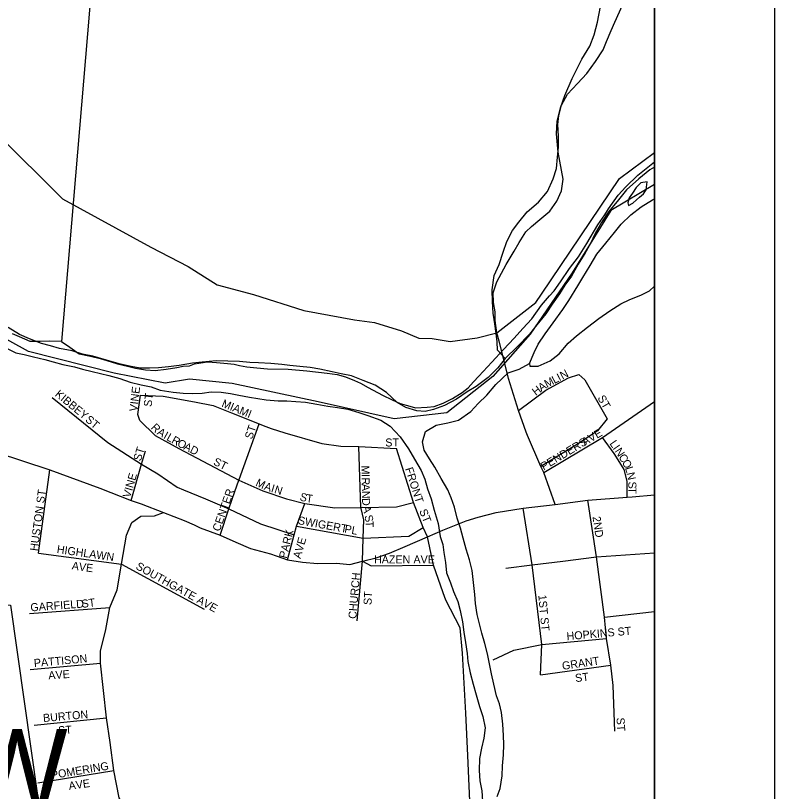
# Model space of a CAD drawing. Extents: x 0 to 34, y -4 to 22.
# Drawn here: x 8.368 to 9, y 16.667 to 17.313 of the extents above; entities that cross this region are included whole.
import ezdxf

# ---------------------------------------------------------------- set-up
doc = ezdxf.new("R2010")
doc.units = 0
for name, color, linetype in [('GM_X_City_Street', 7, 'Continuous'), ('GM_X_City_Street_Text', 7, 'Continuous'), ('GM_X_Corporation', 7, 'Continuous'), ('GM_X_Corporation_Text', 7, 'Continuous'), ('GM_X_County_Road', 7, 'Continuous'), ('GM_X_County_ROW', 7, 'Continuous'), ('GM_X_Major_River', 7, 'Continuous'), ('GM_X_Minor_River', 7, 'Continuous'), ('GM_X_Section', 7, 'Continuous'), ('GM_X_State_Route', 7, 'Continuous'), ('GM_X_Township', 7, 'Continuous'), ('GM_X_US_Route', 7, 'Continuous'), ('SH_Data', 7, 'Continuous'), ('SN_P_Text', 7, 'Continuous')]:
    doc.layers.add(name, color=color, linetype=linetype)

msp = doc.modelspace()

# ---------------------------------------------------------------- linework, layer by layer
at = {"layer": 'GM_X_City_Street'}
msp.add_line((8.85843, 16.81262), (8.9, 16.81728), dxfattribs=at)
for points in [[(8.78674, 16.98474), (8.80951, 17.00166), (8.82863, 17.01177), (8.83701, 17.01462), (8.84223, 17.01019), (8.86072, 16.97763), (8.85266, 16.96768), (8.83737, 16.9574), (8.80546, 16.93796)], [(8.39859, 16.99537), (8.44502, 16.95792), (8.47298, 16.93995), (8.48647, 16.93179), (8.50261, 16.9208), (8.50792, 16.91861)], [(8.47149, 16.97623), (8.46982, 16.98122), (8.47215, 16.99736)], [(8.47215, 16.99736), (8.49113, 16.99653), (8.51709, 16.9917), (8.53256, 16.98871), (8.54788, 16.98271), (8.57085, 16.9734), (8.57441, 16.97211)], [(8.80792, 16.9329), (8.85693, 16.96214), (8.9, 16.99201)], [(8.47149, 16.97623), (8.4843, 16.96391), (8.50394, 16.95309), (8.55395, 16.92649)], [(8.55425, 16.92731), (8.57085, 16.9734)], [(8.57441, 16.97211), (8.581, 16.96974), (8.59231, 16.96591), (8.62327, 16.95708), (8.63892, 16.95492), (8.65389, 16.95459), (8.68518, 16.95292)], [(8.8725, 16.93923), (8.86657, 16.94871), (8.85693, 16.96214)], [(8.46433, 16.90982), (8.47298, 16.93995), (8.47631, 16.95093)], [(8.6558, 16.90311), (8.6556, 16.90393), (8.65389, 16.95459)], [(8.71115, 16.87936), (8.70749, 16.88719), (8.69949, 16.90816), (8.68518, 16.95292)], [(8.87741, 16.91248), (8.87731, 16.92579), (8.87479, 16.93558), (8.8725, 16.93923)], [(8.38722, 16.86588), (8.39659, 16.93528)], [(8.53841, 16.88097), (8.54577, 16.90264), (8.55074, 16.91729), (8.55395, 16.92649), (8.55425, 16.92731)], [(8.55395, 16.92649), (8.57401, 16.91764), (8.59364, 16.91099), (8.60896, 16.90733), (8.63409, 16.90349), (8.6556, 16.90393), (8.68535, 16.90433), (8.69949, 16.90816)], [(8.50792, 16.91861), (8.52641, 16.91099), (8.54577, 16.90264), (8.57201, 16.89035), (8.60016, 16.88123)], [(8.59449, 16.86034), (8.60016, 16.88123), (8.60207, 16.88825), (8.60896, 16.90733)], [(8.8671, 16.7177), (8.86559, 16.75571), (8.86376, 16.77268), (8.8601, 16.79482), (8.85843, 16.81262), (8.85194, 16.86272), (8.84462, 16.90999)], [(8.45661, 16.6587), (8.45445, 16.66217), (8.45001, 16.68493), (8.44697, 16.70815), (8.44392, 16.72884), (8.43897, 16.77442), (8.43894, 16.78418), (8.44325, 16.8022), (8.44661, 16.82062), (8.45267, 16.8352), (8.45638, 16.8567), (8.46053, 16.88077), (8.465, 16.89151), (8.47232, 16.89667), (8.4838, 16.89684), (8.49129, 16.89967)], [(8.65689, 16.85922), (8.65756, 16.87837), (8.65805, 16.89351), (8.6558, 16.90311)], [(8.80518, 16.76469), (8.80618, 16.78982), (8.79836, 16.85606), (8.79087, 16.90333)], [(8.60207, 16.88825), (8.65756, 16.87837), (8.69567, 16.88003), (8.70749, 16.88719)], [(8.72427, 16.83271), (8.71605, 16.8559), (8.71115, 16.87936)], [(8.79835, 16.85606), (8.79836, 16.85606), (8.82365, 16.85922), (8.85194, 16.86272), (8.9, 16.86611)], [(8.38722, 16.86588), (8.45638, 16.8567)], [(8.45638, 16.8567), (8.52523, 16.81923)], [(8.65265, 16.8094), (8.65689, 16.85922)], [(8.65689, 16.85922), (8.66421, 16.85523), (8.71605, 16.8559)], [(8.77622, 16.8534), (8.79835, 16.85606)], [(8.37984, 16.81574), (8.44661, 16.82062)], [(8.76574, 16.77718), (8.78287, 16.78516), (8.80618, 16.78982), (8.8601, 16.79482)], [(8.38019, 16.76902), (8.43897, 16.77442)], [(8.80518, 16.76469), (8.86376, 16.77268)], [(8.3835, 16.72265), (8.44392, 16.72884)], [(8.3866, 16.67458), (8.45001, 16.68493)]]:
    msp.add_lwpolyline(points, dxfattribs=at)
at = {"layer": 'GM_X_Corporation'}
msp.add_lwpolyline([(8.9, 15.91505), (8.9, 17.17268), (8.86365, 17.15124), (8.83148, 17.09921), (8.79666, 17.04827), (8.7655, 17.0128), (8.72719, 16.98276), (8.68332, 16.97765), (8.6202, 16.99174), (8.54854, 17.007), (8.51306, 17.01061), (8.49272, 17.00737), (8.45036, 17.01561), (8.37901, 17.0338), (8.33444, 17.0581), (8.26206, 17.10064), (8.16412, 17.15042), (8.06988, 17.19641), (8.05808, 17.08586), (8.09498, 17.02502), (8.15329, 16.9257), (8.21598, 16.82312), (8.36391, 16.8226), (8.39233, 16.62295)], dxfattribs=at)
at = {"layer": 'GM_X_County_Road'}
for points in [[(8.16162, 17.33442), (8.21917, 17.29622), (8.33224, 17.2399), (8.34171, 17.23144), (8.35262, 17.21493), (8.40719, 17.16075), (8.48075, 17.12065), (8.51172, 17.10458), (8.53602, 17.08917), (8.56635, 17.08122), (8.60808, 17.06776), (8.65047, 17.06002), (8.66696, 17.058), (8.6895, 17.05093), (8.70397, 17.04488), (8.71507, 17.04454), (8.72988, 17.04219), (8.75242, 17.04522), (8.76891, 17.04925), (8.80121, 17.07449), (8.80599, 17.08155)], [(8.80599, 17.08155), (8.87105, 17.17764), (8.9, 17.1995)]]:
    msp.add_lwpolyline(points, dxfattribs=at)
at = {"layer": 'GM_X_County_ROW'}
msp.add_lwpolyline([(8.72549, 16.60607), (8.73149, 16.61464), (8.74254, 16.63166), (8.74682, 16.64674), (8.74471, 16.69729), (8.74316, 16.73269), (8.74034, 16.78248), (8.73836, 16.80364), (8.72637, 16.82677), (8.72427, 16.83271)], dxfattribs=at)
at = {"layer": 'GM_X_Major_River'}
for points in [[(8.9, 17.18709), (8.89614, 17.18495), (8.88711, 17.17742), (8.87671, 17.16833), (8.86896, 17.15863), (8.86178, 17.14999), (8.85593, 17.14105), (8.85061, 17.13183), (8.84691, 17.12363), (8.84215, 17.1152), (8.83657, 17.10652), (8.83096, 17.0965), (8.82541, 17.08889), (8.82094, 17.08178), (8.81483, 17.07312), (8.80954, 17.06496), (8.80207, 17.0558), (8.79599, 17.0482), (8.78581, 17.03749), (8.77566, 17.02786), (8.76957, 17.02026), (8.7616, 17.01217), (8.75151, 17.00467), (8.74416, 17.00004), (8.73517, 16.99412), (8.72513, 16.98876), (8.71622, 16.98551), (8.70921, 16.98381), (8.70227, 16.98425), (8.69297, 16.98716), (8.68585, 16.99135), (8.67697, 16.99959), (8.66749, 17.0057), (8.65742, 17.0097), (8.64788, 17.01341), (8.6391, 17.01524), (8.63164, 17.01676), (8.62153, 17.01915), (8.61353, 17.02042), (8.60472, 17.02117), (8.59645, 17.02218), (8.58978, 17.02288), (8.5807, 17.02365), (8.57027, 17.02417), (8.56332, 17.02462), (8.55451, 17.02537), (8.54488, 17.02561), (8.53525, 17.02585), (8.52345, 17.02481), (8.5154, 17.02394), (8.50437, 17.02208), (8.49551, 17.02097), (8.48719, 17.0201), (8.47969, 17.01976), (8.47193, 17.01995), (8.46447, 17.02121), (8.45436, 17.0236), (8.44373, 17.02654), (8.43257, 17.02976), (8.42379, 17.03158), (8.41529, 17.0342), (8.40464, 17.03634), (8.3972, 17.03839), (8.38976, 17.04045), (8.37968, 17.04418), (8.37148, 17.04786), (8.362, 17.05371)], [(8.89401, 17.17484), (8.88864, 17.17418), (8.88479, 17.17026), (8.88172, 17.16553), (8.87894, 17.16159), (8.87777, 17.15761), (8.87851, 17.15519), (8.88204, 17.15724), (8.88506, 17.1601), (8.88752, 17.16218)], [(8.88752, 17.16218), (8.89108, 17.16503), (8.8933, 17.16818), (8.89401, 17.17484)], [(8.76919, 16.66317), (8.77151, 16.67006), (8.77338, 16.68044), (8.7736, 16.68872), (8.77437, 16.69805), (8.77459, 16.7066), (8.77452, 16.71409), (8.77396, 16.72346), (8.7726, 16.73311), (8.77118, 16.74037), (8.76868, 16.74711), (8.76625, 16.75679), (8.76433, 16.7654), (8.76244, 16.77506), (8.76102, 16.78205), (8.75883, 16.79066), (8.75638, 16.79927), (8.75419, 16.80815), (8.7525, 16.81487), (8.75113, 16.82399), (8.75051, 16.83149), (8.74943, 16.84141), (8.74835, 16.85133), (8.74617, 16.8602), (8.74319, 16.8691), (8.74075, 16.87825), (8.73855, 16.88659), (8.73583, 16.89494), (8.73365, 16.90408), (8.73091, 16.9119), (8.72814, 16.91866), (8.72249, 16.92788), (8.71711, 16.93737), (8.71275, 16.94443), (8.70838, 16.95149), (8.70695, 16.95848), (8.70932, 16.96724), (8.71829, 16.97236), (8.72797, 16.97426), (8.73687, 16.9767), (8.74722, 16.98366), (8.75328, 16.99046), (8.76042, 16.9975), (8.76814, 17.00613), (8.7783, 17.01603), (8.78747, 17.01901), (8.7959, 17.02388), (8.79987, 17.03286), (8.80326, 17.03973), (8.80911, 17.0484), (8.81577, 17.05759), (8.82382, 17.06862), (8.82883, 17.07624), (8.83637, 17.08835), (8.84057, 17.09546), (8.84644, 17.1052), (8.85204, 17.11468), (8.8595, 17.12385), (8.86669, 17.13276), (8.87249, 17.13983), (8.88045, 17.14739), (8.88892, 17.15412), (8.89844, 17.16003), (8.9, 17.16095)], [(8.35837, 17.0375), (8.36841, 17.0327), (8.37533, 17.03119), (8.38305, 17.02939), (8.39262, 17.02702), (8.39953, 17.02524), (8.4075, 17.0229), (8.41709, 17.02106), (8.424, 17.01901), (8.43198, 17.01721), (8.43889, 17.01543), (8.44581, 17.01366), (8.45485, 17.01129), (8.4636, 17.00813), (8.47265, 17.00604), (8.48116, 17.00422), (8.48859, 17.00163), (8.49925, 17.00002), (8.50779, 16.99901), (8.51555, 16.99882), (8.52359, 16.99915), (8.53111, 17.00003), (8.5394, 16.99982), (8.54713, 16.99883), (8.55405, 16.99732), (8.56285, 16.99576), (8.57671, 16.99354), (8.58686, 16.99275), (8.59408, 16.99257), (8.60156, 16.99212), (8.60958, 16.99165), (8.6189, 16.98981), (8.62823, 16.98824), (8.63623, 16.98724), (8.64476, 16.98569), (8.65406, 16.98305), (8.66148, 16.98046), (8.67235, 16.97645), (8.67999, 16.97145), (8.68833, 16.96268), (8.69529, 16.95262), (8.70016, 16.94421), (8.7058, 16.93472), (8.70883, 16.92742), (8.71103, 16.91935), (8.71429, 16.91098), (8.71673, 16.90157), (8.71992, 16.89053), (8.72178, 16.87979), (8.72375, 16.87306), (8.72465, 16.86635), (8.72604, 16.85803), (8.72689, 16.84946), (8.73015, 16.84109), (8.73265, 16.83408), (8.73645, 16.8257), (8.73839, 16.81816), (8.74029, 16.80876), (8.74141, 16.80018), (8.74279, 16.79159), (8.74417, 16.78247), (8.74479, 16.77577), (8.74669, 16.76637), (8.74912, 16.75669), (8.75157, 16.74781), (8.75453, 16.73811), (8.75726, 16.72976), (8.75916, 16.72035), (8.75813, 16.71182), (8.75605, 16.70359), (8.75448, 16.69481), (8.75423, 16.68493), (8.75481, 16.67636), (8.75647, 16.66803), (8.75678, 16.65947)]]:
    msp.add_lwpolyline(points, dxfattribs=at)
at = {"layer": 'GM_X_Minor_River'}
for points in [[(8.77566, 17.02786), (8.76942, 17.03496), (8.76905, 17.04165), (8.76816, 17.04863), (8.7673, 17.05666), (8.76565, 17.06553), (8.76511, 17.07543), (8.76482, 17.08506), (8.76674, 17.09704), (8.77071, 17.10603), (8.77419, 17.11636), (8.7771, 17.12538), (8.78188, 17.13435), (8.78715, 17.14143), (8.79407, 17.15008), (8.80364, 17.15813), (8.8111, 17.16703), (8.81565, 17.17761), (8.81855, 17.18609), (8.81933, 17.19542), (8.82008, 17.20396), (8.82005, 17.21304), (8.81976, 17.22268), (8.82049, 17.23014), (8.82259, 17.23891), (8.82764, 17.24787), (8.8359, 17.25675), (8.84387, 17.2651), (8.85109, 17.27508), (8.85723, 17.28482), (8.86009, 17.2917), (8.86407, 17.30095), (8.86719, 17.30782), (8.87593, 17.32788)], [(8.7959, 17.02388), (8.79637, 17.02146), (8.80333, 17.02155), (8.81334, 17.02584), (8.82073, 17.03181), (8.82818, 17.04071), (8.83503, 17.04669), (8.84431, 17.05394), (8.85387, 17.06118), (8.86287, 17.06764), (8.87211, 17.07329), (8.87944, 17.07711), (8.88863, 17.08063), (8.89595, 17.08419), (8.9, 17.08818)]]:
    msp.add_lwpolyline(points, dxfattribs=at)
at = {"layer": 'GM_X_Section'}
for points in [[(8.46166, 17.69579), (8.40647, 17.04204), (8.39661, 17.04223), (8.38861, 17.04211), (8.38035, 17.042), (8.37136, 17.0459), (8.36554, 17.04841)], [(8.46166, 17.69579), (8.40647, 17.04204), (8.41332, 17.03738), (8.42121, 17.0319), (8.4305, 17.02986), (8.43847, 17.02784), (8.44775, 17.02527), (8.45305, 17.02357), (8.46127, 17.02155), (8.46791, 17.01983), (8.47642, 17.0186), (8.4844, 17.01792), (8.49349, 17.01908), (8.50231, 17.02052), (8.50766, 17.02148), (8.513, 17.02192), (8.51703, 17.02344), (8.52425, 17.02464), (8.52799, 17.0251), (8.53545, 17.02469), (8.5445, 17.02373), (8.55008, 17.02309), (8.5546, 17.0222), (8.56071, 17.02102), (8.56896, 17.02007), (8.57801, 17.01936), (8.59506, 17.01905), (8.61077, 17.01769), (8.62753, 17.01577), (8.63603, 17.01454), (8.64293, 17.01255), (8.65034, 17.00948), (8.65536, 17.00725), (8.66169, 17.00367), (8.67357, 16.99731), (8.68176, 16.99342), (8.68837, 16.99037), (8.69632, 16.98809), (8.7011, 16.98693), (8.71071, 16.98728), (8.71658, 16.98797), (8.7241, 16.99077), (8.7319, 16.99462), (8.74007, 16.99966), (8.74486, 17.00344), (8.74949, 17.00842), (8.75385, 17.01313), (8.76473, 17.02493), (8.77426, 17.03541), (8.78323, 17.04484), (8.79058, 17.05297), (8.79793, 17.06083), (8.80615, 17.07241), (8.81269, 17.08001), (8.8165, 17.08421), (8.82171, 17.09184), (8.82938, 17.1029), (8.83676, 17.11263), (8.8439, 17.12369), (8.85299, 17.13925), (8.85874, 17.1474), (8.86177, 17.15241), (8.86998, 17.16399), (8.87624, 17.1708), (8.88629, 17.18048), (8.9, 17.19176), (8.9, 17.65526)]]:
    msp.add_lwpolyline(points, dxfattribs=at)
at = {"layer": 'GM_X_State_Route'}
for points in [[(8.78313, 17.11715), (8.78737, 17.12434), (8.79297, 17.13326), (8.79765, 17.13793), (8.8045, 17.14361), (8.81299, 17.15058), (8.81885, 17.15896), (8.82256, 17.1674), (8.82419, 17.17724), (8.8228, 17.18476), (8.81977, 17.19981), (8.81861, 17.21507), (8.81918, 17.22547), (8.82191, 17.23661), (8.82542, 17.24693), (8.83144, 17.26092), (8.83966, 17.27697), (8.84613, 17.28801), (8.84987, 17.29725), (8.85259, 17.30786), (8.85511, 17.32087)], [(8.77075, 17.0423), (8.76891, 17.04925), (8.76756, 17.05968), (8.76746, 17.0668), (8.76596, 17.07463), (8.76566, 17.08247), (8.76878, 17.09174), (8.77668, 17.10621), (8.78313, 17.11715)], [(8.79334, 16.96646), (8.78674, 16.98474), (8.77868, 17.01114), (8.77331, 17.03264), (8.77075, 17.0423)], [(8.81733, 16.90632), (8.80792, 16.9329), (8.80546, 16.93796), (8.79433, 16.96372), (8.79334, 16.96646)]]:
    msp.add_lwpolyline(points, dxfattribs=at)
at = {"layer": 'GM_X_Township'}
msp.add_lwpolyline([(8.9, 14.99227), (8.9, 19.07101)], dxfattribs=at)
at = {"layer": 'GM_X_US_Route'}
msp.add_line((8.88139, 16.91283), (8.9, 16.91446), dxfattribs=at)
for points in [[(8.09186, 17.0822), (8.1067, 17.08033), (8.11961, 17.08273), (8.13475, 17.076), (8.14804, 17.06927), (8.16032, 17.06221), (8.1721, 17.05463), (8.18253, 17.04622), (8.19641, 17.03394), (8.21239, 17.01947), (8.23207, 17.00232), (8.24486, 16.99407), (8.26033, 16.98667), (8.29112, 16.97372), (8.32342, 16.96143), (8.35166, 16.94993), (8.39659, 16.93528), (8.4382, 16.91997), (8.46433, 16.90982), (8.47282, 16.90699), (8.49129, 16.89967), (8.50843, 16.89318), (8.51676, 16.88937)], [(8.81733, 16.90632), (8.81733, 16.90632), (8.84462, 16.90999), (8.87741, 16.91248), (8.88139, 16.91283)], [(8.51676, 16.88937), (8.52192, 16.88702), (8.53841, 16.88097), (8.55154, 16.87504), (8.56369, 16.86971), (8.5805, 16.86522), (8.59449, 16.86034), (8.60696, 16.85823), (8.61961, 16.85723), (8.63525, 16.8574), (8.64657, 16.85656), (8.65689, 16.85922), (8.66837, 16.86205), (8.67952, 16.86588), (8.69251, 16.87154), (8.71115, 16.87936), (8.72379, 16.88502), (8.74343, 16.89285), (8.75325, 16.89584), (8.7684, 16.89983), (8.79087, 16.90333), (8.81733, 16.90632)]]:
    msp.add_lwpolyline(points, dxfattribs=at)
at = {"layer": 'SH_Data'}
for p, q in [((9, 21), (9, 14)), ((8.9, 20.9), (8.9, 14.1))]:
    msp.add_line(p, q, dxfattribs=at)
at = {"layer": 'SN_P_Text'}
msp.add_lwpolyline([(8.9, 14.1), (8.9, 20.9), (2.1, 20.9), (2.1, 14.1)], close=True, dxfattribs=at)

# ---------------------------------------------------------------- texts
at = {"layer": 'GM_X_City_Street_Text'}
for s, height, rotation, p in [('I', 0.00667, 27.8215, (8.82093, 17.00885)), ('N', 0.00667, 27.83591, (8.82353, 17.01022)), ('M', 0.00667, 28.27608, (8.81059, 17.00333)), ('L', 0.00667, 27.82342, (8.81678, 17.00666)), ('KIBBEY', 0.006667, 320.47721, (8.40042, 16.9972)), ('VINE', 0.006667, 83.09272, (8.46937, 16.98347)), ('H', 0.00667, 37.34203, (8.80131, 16.99664)), ('A', 0.00667, 34.11447, (8.80589, 17.00014)), ('ST', 0.006667, 82.87834, (8.48133, 16.98734)), ('ST', 0.006667, 299.74321, (8.85245, 16.99509)), ('MIAMI', 0.006667, 337.48165, (8.53915, 16.988)), ('ST', 0.006667, 320.2016, (8.42566, 16.97608)), ('R', 0.00667, 313.64303, (8.48039, 16.97003)), ('A', 0.00667, 327.30315, (8.48537, 16.96511)), ('ST', 0.006667, 71.56067, (8.56505, 16.96025)), ('AVE', 0.006667, 30.25813, (8.84193, 16.95507)), ('I', 0.00667, 331.00122, (8.49071, 16.9617)), ('L', 0.00667, 330.83128, (8.49327, 16.96028)), ('R', 0.00667, 330.82746, (8.49737, 16.958)), ('O', 0.00667, 332.11546, (8.50213, 16.95534)), ('A', 0.00667, 333.40483, (8.50746, 16.95252)), ('ST', 0.006667, 0.00001, (8.67595, 16.95466)), ('PENDERS', 0.006667, 31.1248, (8.80788, 16.93453)), ('L', 0.00667, 304.62951, (8.86236, 16.95705)), ('ST', 0.006667, 72.64519, (8.47235, 16.94205)), ('D', 0.00667, 333.43472, (8.5127, 16.9499)), ('I', 0.00667, 304.49051, (8.86503, 16.95319)), ('N', 0.00667, 303.24748, (8.86667, 16.95081)), ('ST', 0.006667, 333.43495, (8.53219, 16.93986)), ('C', 0.00667, 302.25512, (8.86987, 16.94593)), ('O', 0.00667, 300.18407, (8.87265, 16.94152)), ('M', 0.00667, 271.03832, (8.65608, 16.93876)), ('FRONT', 0.006667, 287.64911, (8.6924, 16.93619)), ('L', 0.00667, 287.51049, (8.87544, 16.9368)), ('VINE', 0.006667, 73.81184, (8.46354, 16.91152)), ('I', 0.00667, 271.05928, (8.65621, 16.93172)), ('N', 0.00667, 282.18027, (8.87681, 16.93249)), ('M', 0.00667, 334.5022, (8.56742, 16.92225)), ('A', 0.00667, 341.23674, (8.57456, 16.91889)), ('R', 0.00667, 271.04428, (8.65626, 16.92879)), ('S', 0.00667, 271.8855, (8.87827, 16.92533)), ('HUSTON ST', 0.006667, 82.40382, (8.38665, 16.86733)), ('CENTER', 0.006667, 70.55794, (8.53807, 16.88342)), ('I', 0.00667, 342.92629, (8.58032, 16.91694)), ('N', 0.00667, 342.89888, (8.58312, 16.91608)), ('A', 0.00667, 271.0521, (8.65636, 16.92351)), ('T', 0.00667, 270.05466, (8.87842, 16.92069)), ('S', 0.00667, 343.80318, (8.60425, 16.90999)), ('T', 0.00667, 351.97337, (8.60977, 16.90846)), ('N', 0.00667, 271.02733, (8.65647, 16.91764)), ('D', 0.00667, 271.93138, (8.65657, 16.91166)), ('A', 0.00667, 282.47772, (8.65694, 16.90447)), ('ST', 0.006667, 291.80393, (8.7041, 16.90107)), ('SWIGERT', 0.006667, 349.77999, (8.60283, 16.89011)), ('S', 0.00667, 281.0259, (8.65859, 16.89705)), ('T', 0.00667, 271.77627, (8.65945, 16.89273)), ('2ND', 0.006667, 278.43021, (8.84849, 16.8961)), ('PARK', 0.006667, 75.96661, (8.59377, 16.86102)), ('PL', 0.006667, 349.3721, (8.64156, 16.88306)), ('AVE', 0.006667, 74.05563, (8.60539, 16.86084)), ('HIGHLAWN', 0.006667, 351.76605, (8.40215, 16.86606)), ('HAZEN', 0.006667, 0.00001, (8.66656, 16.85727)), ('AVE', 0.006667, 0.00001, (8.69941, 16.85727)), ('AVE', 0.006667, 352.14337, (8.41466, 16.85235)), ('SOUTHGATE AVE', 0.0066667, 330.9932, (8.4677, 16.85301)), ('CHURCH', 0.006667, 85.07172, (8.65181, 16.81095)), ('ST', 0.006667, 86.42535, (8.66443, 16.82253)), ('ST', 0.006667, 7.12165, (8.42352, 16.8203)), ('1ST ST', 0.006667, 275.31678, (8.80333, 16.83091)), ('GARFIELD', 0.006667, 4.14549, (8.38076, 16.81738)), ('HOPKINS ST', 0.006667, 5.06344, (8.82719, 16.79332)), ('PATTISON', 0.006667, 5.11765, (8.38367, 16.77103)), ('GRANT', 0.006667, 8.29705, (8.8236, 16.76867)), ('AVE', 0.006667, 3.95062, (8.39564, 16.76076)), ('ST', 0.006667, 7.12165, (8.83444, 16.75847)), ('BURTON', 0.006667, 5.01425, (8.3913, 16.72527)), ('ST', 0.006667, 273.57465, (8.86845, 16.72879)), ('ST', 0.006667, 3.57463, (8.40378, 16.715)), ('POMERING', 0.006667, 9.46331, (8.39825, 16.67774)), ('AVE', 0.006667, 8.12573, (8.4128, 16.66873))]:
    msp.add_text(s, height=height, rotation=rotation, dxfattribs=at).set_placement(p)
at = {"layer": 'GM_X_Corporation_Text'}
msp.add_text('MORROW', height=0.066667, rotation=0.00001, dxfattribs=at).set_placement((7.98561, 16.6527))

doc.saveas('drawing.dxf')
